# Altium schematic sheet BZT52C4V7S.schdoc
size 127 x 101 mm
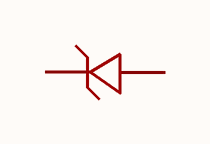
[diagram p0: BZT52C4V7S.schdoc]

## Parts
ZD?  bzt52c4v7s_c22611  [SOD-323_L1.8-W1.3-LS2.5-RD]  (value not drawn)

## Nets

Not connected (* = marked no-connect by the designer): ZD? 1(K) 2(A)

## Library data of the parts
ZD? = bzt52c4v7s_c22611: 二极管配置:1个独立式;稳压值(标称值):4.7V;稳压值(范围):4.4V~5V;耗散功率(Pd):200mW;; Manufacturer: CJ(江苏长电/长晶); AddInBom: yes; ModelId: db63db13d9e342eb939127d413d6200b; ModelTransform: 104.3305,51.181,0,0,0,0,0,-0.004,0; Diode Configuration: 1个独立式; Zener Voltage(Nom): 4.7V; Reverse Leakage Current (Ir): 3uA@2V; Pd - Power Dissipation: 200mW; Impedance(Zzt): 80Ω; Impedance(Zzk): 500Ω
